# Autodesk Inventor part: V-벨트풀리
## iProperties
Company: 한국ATC센터
Created: 2014-07
Part Number: V-벨트풀리
Document SubType Name: Modeling
Designer: KYOUNG IL JANG
Density: 7.86 g/cm^3
Material: 강, 연강
Mass: 1497.56 g
Surface Area: 466.268 cm^2
Volume: 190.529 cm^3
Author: KYOUNG IL JANG
